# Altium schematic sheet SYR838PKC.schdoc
size 127 x 101 mm
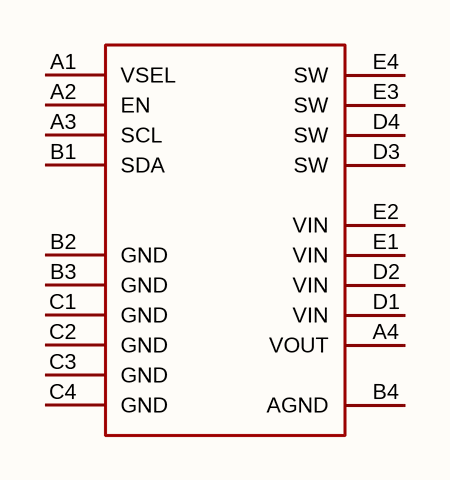
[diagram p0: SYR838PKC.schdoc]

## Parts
U?  syr838pkc  [BGA-20_L15.6-W2.0-R4-C6-P0.40-BL]  (value not drawn)

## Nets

Not connected (* = marked no-connect by the designer): U? A1(VSEL) A2(EN) A3(SCL) A4(VOUT) B1(SDA) B2(GND) B3(GND) B4(AGND) C1(GND) C2(GND) C3(GND) C4(GND) D1(VIN) D2(VIN) D3(SW) D4(SW) E1(VIN) E2(VIN) E3(SW) E4(SW)

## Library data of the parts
U? = syr838pkc: 功能类型:降压型;工作电压:2.6V~5.5V;输出电压:712.5mV~1.5V;输出电流:6A;输出类型:可调;; Manufacturer: Silergy(矽力杰); AddInBom: yes; ModelId: 1e7a9594aa15460aaca696d1d93a5a6f; ModelName: BGA-20_L2.0-W1.6-H0.6-P0.40; ModelTransform: 78.74,61.4172,0,0,0,0,-0.001,-0.003,-1.969; Function: 降压型; Output Current: 6A; Frequency - Switching: 2.4MHz; Synchronous Rectifier: 是; Number of Outputs: 1; Topology: 降压式; Quiescent Current: 65uA; Switch tube (built-in/external): 内置; Output Type: 可调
